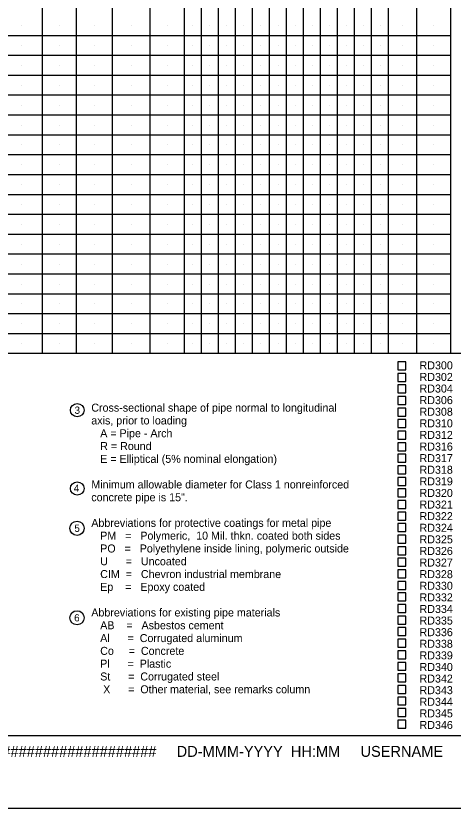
# Model space of a CAD drawing. Extents: x -1700 to 0, y 0 to 1100.
# Drawn here: x -1388 to -1087, y 0 to 545 of the extents above; entities that cross this region are included whole.
import ezdxf

# ---------------------------------------------------------------- set-up
doc = ezdxf.new("R2010")
doc.units = 0
for name, color, linetype in [('#plot_border', 7, 'Continuous'), ('#plot_shape', 7, 'Continuous'), ('P_ODOT_PLAN_Border', 7, 'Continuous'), ('P_ODOT_PLAN_General', 7, 'Continuous'), ('P_RDWY_PLAN_NotesTx', 7, 'Continuous')]:
    doc.layers.add(name, color=color, linetype=linetype)

msp = doc.modelspace()

# ---------------------------------------------------------------- linework, layer by layer
at = {"layer": '#plot_shape'}
msp.add_lwpolyline([(-1700, 0), (0, 0), (0, 1100), (-1700, 1100)], close=True, dxfattribs=at)
at = {"layer": 'P_ODOT_PLAN_Border'}
msp.add_lwpolyline([(-1625, 50), (-25, 50), (-25, 1050), (-1625, 1050)], close=True, dxfattribs=at)
at = {"layer": 'P_ODOT_PLAN_General'}
for p, q in [((-1271.83, 312.45), (-1271.83, 1050)), ((-1088.42, 312.45), (-1088.42, 1050)), ((-1260.12, 312.45), (-1260.12, 1034.39)), ((-1248.42, 312.45), (-1248.42, 1034.39)), ((-1236.71, 312.45), (-1236.71, 1034.39)), ((-1225, 312.45), (-1225, 1034.39)), ((-1213.3, 312.45), (-1213.3, 1034.39)), ((-1201.59, 312.45), (-1201.59, 1034.39)), ((-1189.88, 312.45), (-1189.88, 1034.39)), ((-1178.17, 312.45), (-1178.17, 1034.39)), ((-1166.47, 312.45), (-1166.47, 1034.39)), ((-1154.76, 312.45), (-1154.76, 1034.39)), ((-1143.05, 312.45), (-1143.05, 1034.39)), ((-1131.35, 312.45), (-1131.35, 1034.39)), ((-1111.83, 312.45), (-1111.83, 1034.39)), ((-1369.39, 312.45), (-1369.39, 1014.88)), ((-1345.98, 312.45), (-1345.98, 1014.88)), ((-1295.47, 312.45), (-1295.47, 952.44)), ((-1321.23, 312.45), (-1321.23, 913.42)), ((-1384.03, 537.81), (-1384.03, 537.81)), ((-1357.68, 537.81), (-1357.68, 537.81)), ((-1333.61, 537.81), (-1333.61, 537.81)), ((-1308.35, 537.81), (-1308.35, 537.81)), ((-1283.65, 537.81), (-1283.65, 537.81)), ((-1265.98, 537.81), (-1265.98, 537.81)), ((-1254.27, 537.81), (-1254.27, 537.81)), ((-1242.56, 537.81), (-1242.56, 537.81)), ((-1230.86, 537.81), (-1230.86, 537.81)), ((-1219.15, 537.81), (-1219.15, 537.81)), ((-1207.44, 537.81), (-1207.44, 537.81)), ((-1195.73, 537.81), (-1195.73, 537.81)), ((-1184.03, 537.81), (-1184.03, 537.81)), ((-1172.32, 537.81), (-1172.32, 537.81)), ((-1160.61, 537.81), (-1160.61, 537.81)), ((-1148.91, 537.81), (-1148.91, 537.81)), ((-1137.2, 537.81), (-1137.2, 537.81)), ((-1121.59, 537.81), (-1121.59, 537.81)), ((-1100.13, 537.81), (-1100.13, 537.81)), ((-1088.42, 530.98), (-1398.66, 530.98)), ((-1384.03, 524.15), (-1384.03, 524.15)), ((-1357.68, 524.15), (-1357.68, 524.15)), ((-1333.61, 524.15), (-1333.61, 524.15)), ((-1308.35, 524.15), (-1308.35, 524.15)), ((-1283.65, 524.15), (-1283.65, 524.15)), ((-1265.98, 524.15), (-1265.98, 524.15)), ((-1254.27, 524.15), (-1254.27, 524.15)), ((-1242.56, 524.15), (-1242.56, 524.15)), ((-1230.86, 524.15), (-1230.86, 524.15)), ((-1219.15, 524.15), (-1219.15, 524.15)), ((-1207.44, 524.15), (-1207.44, 524.15)), ((-1195.73, 524.15), (-1195.73, 524.15)), ((-1184.03, 524.15), (-1184.03, 524.15)), ((-1172.32, 524.15), (-1172.32, 524.15)), ((-1160.61, 524.15), (-1160.61, 524.15)), ((-1148.91, 524.15), (-1148.91, 524.15)), ((-1137.2, 524.15), (-1137.2, 524.15)), ((-1121.59, 524.15), (-1121.59, 524.15)), ((-1100.13, 524.15), (-1100.13, 524.15)), ((-1088.42, 517.32), (-1398.66, 517.32)), ((-1384.03, 510.49), (-1384.03, 510.49)), ((-1357.68, 510.49), (-1357.68, 510.49)), ((-1333.61, 510.49), (-1333.61, 510.49)), ((-1308.35, 510.49), (-1308.35, 510.49)), ((-1283.65, 510.49), (-1283.65, 510.49)), ((-1265.98, 510.49), (-1265.98, 510.49)), ((-1254.27, 510.49), (-1254.27, 510.49)), ((-1242.56, 510.49), (-1242.56, 510.49)), ((-1230.86, 510.49), (-1230.86, 510.49)), ((-1219.15, 510.49), (-1219.15, 510.49)), ((-1207.44, 510.49), (-1207.44, 510.49)), ((-1195.73, 510.49), (-1195.73, 510.49)), ((-1184.03, 510.49), (-1184.03, 510.49)), ((-1172.32, 510.49), (-1172.32, 510.49)), ((-1160.61, 510.49), (-1160.61, 510.49)), ((-1148.91, 510.49), (-1148.91, 510.49)), ((-1137.2, 510.49), (-1137.2, 510.49)), ((-1121.59, 510.49), (-1121.59, 510.49)), ((-1100.13, 510.49), (-1100.13, 510.49)), ((-1088.42, 503.66), (-1398.66, 503.66)), ((-1384.03, 496.83), (-1384.03, 496.83)), ((-1357.68, 496.83), (-1357.68, 496.83)), ((-1333.61, 496.83), (-1333.61, 496.83)), ((-1308.35, 496.83), (-1308.35, 496.83)), ((-1283.65, 496.83), (-1283.65, 496.83)), ((-1265.98, 496.83), (-1265.98, 496.83)), ((-1254.27, 496.83), (-1254.27, 496.83)), ((-1242.56, 496.83), (-1242.56, 496.83)), ((-1230.86, 496.83), (-1230.86, 496.83)), ((-1219.15, 496.83), (-1219.15, 496.83)), ((-1207.44, 496.83), (-1207.44, 496.83)), ((-1195.73, 496.83), (-1195.73, 496.83)), ((-1184.03, 496.83), (-1184.03, 496.83)), ((-1172.32, 496.83), (-1172.32, 496.83)), ((-1160.61, 496.83), (-1160.61, 496.83)), ((-1148.91, 496.83), (-1148.91, 496.83)), ((-1137.2, 496.83), (-1137.2, 496.83)), ((-1121.59, 496.83), (-1121.59, 496.83)), ((-1100.13, 496.83), (-1100.13, 496.83)), ((-1088.42, 490.01), (-1398.66, 490.01)), ((-1384.03, 483.18), (-1384.03, 483.18)), ((-1357.68, 483.18), (-1357.68, 483.18)), ((-1333.61, 483.18), (-1333.61, 483.18)), ((-1308.35, 483.18), (-1308.35, 483.18)), ((-1283.65, 483.18), (-1283.65, 483.18)), ((-1265.98, 483.18), (-1265.98, 483.18)), ((-1254.27, 483.18), (-1254.27, 483.18)), ((-1242.56, 483.18), (-1242.56, 483.18)), ((-1230.86, 483.18), (-1230.86, 483.18)), ((-1219.15, 483.18), (-1219.15, 483.18)), ((-1207.44, 483.18), (-1207.44, 483.18)), ((-1195.73, 483.18), (-1195.73, 483.18)), ((-1184.03, 483.18), (-1184.03, 483.18)), ((-1172.32, 483.18), (-1172.32, 483.18)), ((-1160.61, 483.18), (-1160.61, 483.18)), ((-1148.91, 483.18), (-1148.91, 483.18)), ((-1137.2, 483.18), (-1137.2, 483.18)), ((-1121.59, 483.18), (-1121.59, 483.18)), ((-1100.13, 483.18), (-1100.13, 483.18)), ((-1088.42, 476.35), (-1398.66, 476.35)), ((-1384.03, 469.52), (-1384.03, 469.52)), ((-1357.68, 469.52), (-1357.68, 469.52)), ((-1333.61, 469.52), (-1333.61, 469.52)), ((-1308.35, 469.52), (-1308.35, 469.52)), ((-1283.65, 469.52), (-1283.65, 469.52)), ((-1265.98, 469.52), (-1265.98, 469.52)), ((-1254.27, 469.52), (-1254.27, 469.52)), ((-1242.56, 469.52), (-1242.56, 469.52)), ((-1230.86, 469.52), (-1230.86, 469.52)), ((-1219.15, 469.52), (-1219.15, 469.52)), ((-1207.44, 469.52), (-1207.44, 469.52)), ((-1195.73, 469.52), (-1195.73, 469.52)), ((-1184.03, 469.52), (-1184.03, 469.52)), ((-1172.32, 469.52), (-1172.32, 469.52)), ((-1160.61, 469.52), (-1160.61, 469.52)), ((-1148.91, 469.52), (-1148.91, 469.52)), ((-1137.2, 469.52), (-1137.2, 469.52)), ((-1121.59, 469.52), (-1121.59, 469.52)), ((-1100.13, 469.52), (-1100.13, 469.52)), ((-1088.42, 462.69), (-1398.66, 462.69)), ((-1384.03, 455.86), (-1384.03, 455.86)), ((-1357.68, 455.86), (-1357.68, 455.86)), ((-1333.61, 455.86), (-1333.61, 455.86)), ((-1308.35, 455.86), (-1308.35, 455.86)), ((-1283.65, 455.86), (-1283.65, 455.86)), ((-1265.98, 455.86), (-1265.98, 455.86)), ((-1254.27, 455.86), (-1254.27, 455.86)), ((-1242.56, 455.86), (-1242.56, 455.86)), ((-1230.86, 455.86), (-1230.86, 455.86)), ((-1219.15, 455.86), (-1219.15, 455.86)), ((-1207.44, 455.86), (-1207.44, 455.86)), ((-1195.73, 455.86), (-1195.73, 455.86)), ((-1184.03, 455.86), (-1184.03, 455.86)), ((-1172.32, 455.86), (-1172.32, 455.86)), ((-1160.61, 455.86), (-1160.61, 455.86)), ((-1148.91, 455.86), (-1148.91, 455.86)), ((-1137.2, 455.86), (-1137.2, 455.86)), ((-1121.59, 455.86), (-1121.59, 455.86)), ((-1100.13, 455.86), (-1100.13, 455.86)), ((-1088.42, 449.03), (-1398.66, 449.03)), ((-1384.03, 442.2), (-1384.03, 442.2)), ((-1357.68, 442.2), (-1357.68, 442.2)), ((-1333.61, 442.2), (-1333.61, 442.2)), ((-1308.35, 442.2), (-1308.35, 442.2)), ((-1283.65, 442.2), (-1283.65, 442.2)), ((-1265.98, 442.2), (-1265.98, 442.2)), ((-1254.27, 442.2), (-1254.27, 442.2)), ((-1242.56, 442.2), (-1242.56, 442.2)), ((-1230.86, 442.2), (-1230.86, 442.2)), ((-1219.15, 442.2), (-1219.15, 442.2)), ((-1207.44, 442.2), (-1207.44, 442.2)), ((-1195.73, 442.2), (-1195.73, 442.2)), ((-1184.03, 442.2), (-1184.03, 442.2)), ((-1172.32, 442.2), (-1172.32, 442.2)), ((-1160.61, 442.2), (-1160.61, 442.2)), ((-1148.91, 442.2), (-1148.91, 442.2)), ((-1137.2, 442.2), (-1137.2, 442.2)), ((-1121.59, 442.2), (-1121.59, 442.2)), ((-1100.13, 442.2), (-1100.13, 442.2)), ((-1088.42, 435.37), (-1398.66, 435.37)), ((-1384.03, 428.54), (-1384.03, 428.54)), ((-1357.68, 428.54), (-1357.68, 428.54)), ((-1333.61, 428.54), (-1333.61, 428.54)), ((-1308.35, 428.54), (-1308.35, 428.54)), ((-1283.65, 428.54), (-1283.65, 428.54)), ((-1265.98, 428.54), (-1265.98, 428.54)), ((-1254.27, 428.54), (-1254.27, 428.54)), ((-1242.56, 428.54), (-1242.56, 428.54)), ((-1230.86, 428.54), (-1230.86, 428.54)), ((-1219.15, 428.54), (-1219.15, 428.54)), ((-1207.44, 428.54), (-1207.44, 428.54)), ((-1195.73, 428.54), (-1195.73, 428.54)), ((-1184.03, 428.54), (-1184.03, 428.54)), ((-1172.32, 428.54), (-1172.32, 428.54)), ((-1160.61, 428.54), (-1160.61, 428.54)), ((-1148.91, 428.54), (-1148.91, 428.54)), ((-1137.2, 428.54), (-1137.2, 428.54)), ((-1121.59, 428.54), (-1121.59, 428.54)), ((-1100.13, 428.54), (-1100.13, 428.54)), ((-1088.42, 421.71), (-1398.66, 421.71)), ((-1384.03, 414.88), (-1384.03, 414.88)), ((-1357.68, 414.88), (-1357.68, 414.88)), ((-1333.61, 414.88), (-1333.61, 414.88)), ((-1308.35, 414.88), (-1308.35, 414.88)), ((-1283.65, 414.88), (-1283.65, 414.88)), ((-1265.98, 414.88), (-1265.98, 414.88)), ((-1254.27, 414.88), (-1254.27, 414.88)), ((-1242.56, 414.88), (-1242.56, 414.88)), ((-1230.86, 414.88), (-1230.86, 414.88)), ((-1219.15, 414.88), (-1219.15, 414.88)), ((-1207.44, 414.88), (-1207.44, 414.88)), ((-1195.73, 414.88), (-1195.73, 414.88)), ((-1184.03, 414.88), (-1184.03, 414.88)), ((-1172.32, 414.88), (-1172.32, 414.88)), ((-1160.61, 414.88), (-1160.61, 414.88)), ((-1148.91, 414.88), (-1148.91, 414.88)), ((-1137.2, 414.88), (-1137.2, 414.88)), ((-1121.59, 414.88), (-1121.59, 414.88)), ((-1100.13, 414.88), (-1100.13, 414.88)), ((-1088.42, 408.06), (-1398.66, 408.06)), ((-1384.03, 401.23), (-1384.03, 401.23)), ((-1357.68, 401.23), (-1357.68, 401.23)), ((-1333.61, 401.23), (-1333.61, 401.23)), ((-1308.35, 401.23), (-1308.35, 401.23)), ((-1283.65, 401.23), (-1283.65, 401.23)), ((-1265.98, 401.23), (-1265.98, 401.23)), ((-1254.27, 401.23), (-1254.27, 401.23)), ((-1242.56, 401.23), (-1242.56, 401.23)), ((-1230.86, 401.23), (-1230.86, 401.23)), ((-1219.15, 401.23), (-1219.15, 401.23)), ((-1207.44, 401.23), (-1207.44, 401.23)), ((-1195.73, 401.23), (-1195.73, 401.23)), ((-1184.03, 401.23), (-1184.03, 401.23)), ((-1172.32, 401.23), (-1172.32, 401.23)), ((-1160.61, 401.23), (-1160.61, 401.23)), ((-1148.91, 401.23), (-1148.91, 401.23)), ((-1137.2, 401.23), (-1137.2, 401.23)), ((-1121.59, 401.23), (-1121.59, 401.23)), ((-1100.13, 401.23), (-1100.13, 401.23)), ((-1088.42, 394.4), (-1398.66, 394.4)), ((-1384.03, 387.57), (-1384.03, 387.57)), ((-1357.68, 387.57), (-1357.68, 387.57)), ((-1333.61, 387.57), (-1333.61, 387.57)), ((-1308.35, 387.57), (-1308.35, 387.57)), ((-1283.65, 387.57), (-1283.65, 387.57)), ((-1265.98, 387.57), (-1265.98, 387.57)), ((-1254.27, 387.57), (-1254.27, 387.57)), ((-1242.56, 387.57), (-1242.56, 387.57)), ((-1230.86, 387.57), (-1230.86, 387.57)), ((-1219.15, 387.57), (-1219.15, 387.57)), ((-1207.44, 387.57), (-1207.44, 387.57)), ((-1195.73, 387.57), (-1195.73, 387.57)), ((-1184.03, 387.57), (-1184.03, 387.57)), ((-1172.32, 387.57), (-1172.32, 387.57)), ((-1160.61, 387.57), (-1160.61, 387.57)), ((-1148.91, 387.57), (-1148.91, 387.57)), ((-1137.2, 387.57), (-1137.2, 387.57)), ((-1121.59, 387.57), (-1121.59, 387.57)), ((-1100.13, 387.57), (-1100.13, 387.57)), ((-1088.42, 380.74), (-1398.66, 380.74)), ((-1384.03, 373.91), (-1384.03, 373.91)), ((-1357.68, 373.91), (-1357.68, 373.91)), ((-1333.61, 373.91), (-1333.61, 373.91)), ((-1308.35, 373.91), (-1308.35, 373.91)), ((-1283.65, 373.91), (-1283.65, 373.91)), ((-1265.98, 373.91), (-1265.98, 373.91)), ((-1254.27, 373.91), (-1254.27, 373.91)), ((-1242.56, 373.91), (-1242.56, 373.91)), ((-1230.86, 373.91), (-1230.86, 373.91)), ((-1219.15, 373.91), (-1219.15, 373.91)), ((-1207.44, 373.91), (-1207.44, 373.91)), ((-1195.73, 373.91), (-1195.73, 373.91)), ((-1184.03, 373.91), (-1184.03, 373.91)), ((-1172.32, 373.91), (-1172.32, 373.91)), ((-1160.61, 373.91), (-1160.61, 373.91)), ((-1148.91, 373.91), (-1148.91, 373.91)), ((-1137.2, 373.91), (-1137.2, 373.91)), ((-1121.59, 373.91), (-1121.59, 373.91)), ((-1100.13, 373.91), (-1100.13, 373.91)), ((-1088.42, 367.08), (-1398.66, 367.08)), ((-1384.03, 360.25), (-1384.03, 360.25)), ((-1357.68, 360.25), (-1357.68, 360.25)), ((-1333.61, 360.25), (-1333.61, 360.25)), ((-1308.35, 360.25), (-1308.35, 360.25)), ((-1283.65, 360.25), (-1283.65, 360.25)), ((-1265.98, 360.25), (-1265.98, 360.25)), ((-1254.27, 360.25), (-1254.27, 360.25)), ((-1242.56, 360.25), (-1242.56, 360.25)), ((-1230.86, 360.25), (-1230.86, 360.25)), ((-1219.15, 360.25), (-1219.15, 360.25)), ((-1207.44, 360.25), (-1207.44, 360.25)), ((-1195.73, 360.25), (-1195.73, 360.25)), ((-1184.03, 360.25), (-1184.03, 360.25)), ((-1172.32, 360.25), (-1172.32, 360.25)), ((-1160.61, 360.25), (-1160.61, 360.25)), ((-1148.91, 360.25), (-1148.91, 360.25)), ((-1137.2, 360.25), (-1137.2, 360.25)), ((-1121.59, 360.25), (-1121.59, 360.25)), ((-1100.13, 360.25), (-1100.13, 360.25)), ((-1088.42, 353.42), (-1398.66, 353.42)), ((-1384.03, 346.59), (-1384.03, 346.59)), ((-1357.68, 346.59), (-1357.68, 346.59)), ((-1333.61, 346.59), (-1333.61, 346.59)), ((-1308.35, 346.59), (-1308.35, 346.59)), ((-1283.65, 346.59), (-1283.65, 346.59)), ((-1265.98, 346.59), (-1265.98, 346.59)), ((-1254.27, 346.59), (-1254.27, 346.59)), ((-1242.56, 346.59), (-1242.56, 346.59)), ((-1230.86, 346.59), (-1230.86, 346.59)), ((-1219.15, 346.59), (-1219.15, 346.59)), ((-1207.44, 346.59), (-1207.44, 346.59)), ((-1195.73, 346.59), (-1195.73, 346.59)), ((-1184.03, 346.59), (-1184.03, 346.59)), ((-1172.32, 346.59), (-1172.32, 346.59)), ((-1160.61, 346.59), (-1160.61, 346.59)), ((-1148.91, 346.59), (-1148.91, 346.59)), ((-1137.2, 346.59), (-1137.2, 346.59)), ((-1121.59, 346.59), (-1121.59, 346.59)), ((-1100.13, 346.59), (-1100.13, 346.59)), ((-1088.42, 339.76), (-1398.66, 339.76)), ((-1384.03, 332.93), (-1384.03, 332.93)), ((-1357.68, 332.93), (-1357.68, 332.93)), ((-1333.61, 332.93), (-1333.61, 332.93)), ((-1308.35, 332.93), (-1308.35, 332.93)), ((-1283.65, 332.93), (-1283.65, 332.93)), ((-1265.98, 332.93), (-1265.98, 332.93)), ((-1254.27, 332.93), (-1254.27, 332.93)), ((-1242.56, 332.93), (-1242.56, 332.93)), ((-1230.86, 332.93), (-1230.86, 332.93)), ((-1219.15, 332.93), (-1219.15, 332.93)), ((-1207.44, 332.93), (-1207.44, 332.93)), ((-1195.73, 332.93), (-1195.73, 332.93)), ((-1184.03, 332.93), (-1184.03, 332.93)), ((-1172.32, 332.93), (-1172.32, 332.93)), ((-1160.61, 332.93), (-1160.61, 332.93)), ((-1148.91, 332.93), (-1148.91, 332.93)), ((-1137.2, 332.93), (-1137.2, 332.93)), ((-1121.59, 332.93), (-1121.59, 332.93)), ((-1100.13, 332.93), (-1100.13, 332.93)), ((-1088.42, 326.1), (-1398.66, 326.1)), ((-1384.03, 319.28), (-1384.03, 319.28)), ((-1357.68, 319.28), (-1357.68, 319.28)), ((-1333.61, 319.28), (-1333.61, 319.28)), ((-1308.35, 319.28), (-1308.35, 319.28)), ((-1283.65, 319.28), (-1283.65, 319.28)), ((-1265.98, 319.28), (-1265.98, 319.28)), ((-1254.27, 319.28), (-1254.27, 319.28)), ((-1242.56, 319.28), (-1242.56, 319.28)), ((-1230.86, 319.28), (-1230.86, 319.28)), ((-1219.15, 319.28), (-1219.15, 319.28)), ((-1207.44, 319.28), (-1207.44, 319.28)), ((-1195.73, 319.28), (-1195.73, 319.28)), ((-1184.03, 319.28), (-1184.03, 319.28)), ((-1172.32, 319.28), (-1172.32, 319.28)), ((-1160.61, 319.28), (-1160.61, 319.28)), ((-1148.91, 319.28), (-1148.91, 319.28)), ((-1137.2, 319.28), (-1137.2, 319.28)), ((-1121.59, 319.28), (-1121.59, 319.28)), ((-1100.13, 319.28), (-1100.13, 319.28)), ((-25.02, 312.45), (-1625, 312.45))]:
    msp.add_line(p, q, dxfattribs=at)
at = {"layer": 'P_RDWY_PLAN_NotesTx'}
for points in [[(-1119.52, 306.81), (-1124.99, 306.81), (-1124.99, 301.34), (-1119.52, 301.34)], [(-1119.52, 298.86), (-1124.99, 298.86), (-1124.99, 293.39), (-1119.52, 293.39)], [(-1119.52, 290.92), (-1124.99, 290.92), (-1124.99, 285.45), (-1119.52, 285.45)], [(-1119.52, 282.97), (-1124.99, 282.97), (-1124.99, 277.5), (-1119.52, 277.5)], [(-1119.52, 275.03), (-1124.99, 275.03), (-1124.99, 269.56), (-1119.52, 269.56)], [(-1119.52, 267.08), (-1124.99, 267.08), (-1124.99, 261.61), (-1119.52, 261.61)], [(-1119.52, 259.14), (-1124.99, 259.14), (-1124.99, 253.67), (-1119.52, 253.67)], [(-1119.52, 251.19), (-1124.99, 251.19), (-1124.99, 245.72), (-1119.52, 245.72)], [(-1119.52, 243.25), (-1124.99, 243.25), (-1124.99, 237.78), (-1119.52, 237.78)], [(-1119.52, 235.3), (-1124.99, 235.3), (-1124.99, 229.83), (-1119.52, 229.83)], [(-1119.52, 227.35), (-1124.99, 227.35), (-1124.99, 221.88), (-1119.52, 221.88)], [(-1119.52, 219.41), (-1124.99, 219.41), (-1124.99, 213.94), (-1119.52, 213.94)], [(-1119.52, 211.46), (-1124.99, 211.46), (-1124.99, 205.99), (-1119.52, 205.99)], [(-1119.52, 203.52), (-1124.99, 203.52), (-1124.99, 198.05), (-1119.52, 198.05)], [(-1119.52, 195.57), (-1124.99, 195.57), (-1124.99, 190.1), (-1119.52, 190.1)], [(-1119.52, 187.63), (-1124.99, 187.63), (-1124.99, 182.16), (-1119.52, 182.16)], [(-1119.52, 179.68), (-1124.99, 179.68), (-1124.99, 174.21), (-1119.52, 174.21)], [(-1119.52, 171.74), (-1124.99, 171.74), (-1124.99, 166.27), (-1119.52, 166.27)], [(-1119.52, 163.79), (-1124.99, 163.79), (-1124.99, 158.32), (-1119.52, 158.32)], [(-1119.52, 155.85), (-1124.99, 155.85), (-1124.99, 150.38), (-1119.52, 150.38)], [(-1119.52, 147.9), (-1124.99, 147.9), (-1124.99, 142.43), (-1119.52, 142.43)], [(-1119.52, 139.96), (-1124.99, 139.96), (-1124.99, 134.49), (-1119.52, 134.49)], [(-1119.52, 132.01), (-1124.99, 132.01), (-1124.99, 126.54), (-1119.52, 126.54)], [(-1119.52, 124.07), (-1124.99, 124.07), (-1124.99, 118.6), (-1119.52, 118.6)], [(-1119.52, 116.12), (-1124.99, 116.12), (-1124.99, 110.65), (-1119.52, 110.65)], [(-1119.52, 108.18), (-1124.99, 108.18), (-1124.99, 102.71), (-1119.52, 102.71)], [(-1119.52, 100.23), (-1124.99, 100.23), (-1124.99, 94.76), (-1119.52, 94.76)], [(-1119.52, 92.29), (-1124.99, 92.29), (-1124.99, 86.82), (-1119.52, 86.82)], [(-1119.52, 84.34), (-1124.99, 84.34), (-1124.99, 78.87), (-1119.52, 78.87)], [(-1119.52, 76.39), (-1124.99, 76.39), (-1124.99, 70.92), (-1119.52, 70.92)], [(-1119.52, 68.45), (-1124.99, 68.45), (-1124.99, 62.98), (-1119.52, 62.98)], [(-1119.52, 60.5), (-1124.99, 60.5), (-1124.99, 55.03), (-1119.52, 55.03)]]:
    msp.add_lwpolyline(points, close=True, dxfattribs=at)
for centre in [(-1345.73, 192.4), (-1345.73, 130.86)]:
    msp.add_circle(centre, 4.88, dxfattribs=at)
for centre in [(-1345.58, 273.57), (-1345.58, 219.71)]:
    msp.add_ellipse(centre, major_axis=(4.68, 0), ratio=0.960077, dxfattribs=at)

# ---------------------------------------------------------------- texts
at = {"layer": '#plot_border'}
msp.add_text('THIS IS THE FILENAME LOCATION ##############################     DD-MMM-YYYY  HH:MM     USERNAME', height=7.5, dxfattribs=at).set_placement((-1626.17, 35.27))
at = {"layer": 'P_RDWY_PLAN_NotesTx'}
for s, height, p in [('RD300', 5.5, (-1110.06, 301.65)), ('RD302', 5.5, (-1110.06, 293.67)), ('RD304', 5.5, (-1110.06, 285.7)), ('RD306', 5.5, (-1110.06, 277.72)), ('Cross-sectional shape of pipe normal to longitudinal', 5.5, (-1335.89, 272.56)), ('3', 5, (-1347.39, 271.07)), ('RD308', 5.5, (-1110.06, 269.75)), ('axis, prior to loading', 5.5, (-1335.89, 263.76)), ('RD310', 5.5, (-1110.06, 261.77)), ('   A = Pipe - Arch', 5.5, (-1335.89, 254.96)), ('RD312', 5.5, (-1110.06, 253.8)), ('   R = Round', 5.5, (-1335.89, 246.16)), ('RD316', 5.5, (-1110.06, 245.82)), ('   E = Elliptical (5% nominal elongation)', 5.5, (-1335.89, 237.36)), ('RD317', 5.5, (-1110.06, 237.85)), ('RD318', 5.5, (-1110.06, 229.87)), ('Minimum allowable diameter for Class 1 nonreinforced', 5.5, (-1335.89, 219.76)), ('RD319', 5.5, (-1110.06, 221.9)), ('4', 5, (-1347.93, 217.45)), ('RD320', 5.5, (-1110.06, 213.92)), ('concrete pipe is 15".', 5.5, (-1335.89, 210.96)), ('RD321', 5.5, (-1110.06, 205.95)), ('RD322', 5.5, (-1110.06, 197.97)), ('Abbreviations for protective coatings for metal pipe', 5.5, (-1335.89, 193.36)), ('5', 5, (-1347.51, 189.9)), ('RD324', 5.5, (-1110.06, 190)), ('   PM   =   Polymeric,  10 Mil. thkn. coated both sides', 5.5, (-1335.89, 184.56)), ('RD325', 5.5, (-1110.06, 182.02)), ('   PO   =   Polyethylene inside lining, polymeric outside', 5.5, (-1335.89, 175.76)), ('RD326', 5.5, (-1110.06, 174.05)), ('   U      =   Uncoated', 5.5, (-1335.89, 166.96)), ('RD327', 5.5, (-1110.06, 166.07)), ('   CIM  =   Chevron industrial membrane', 5.5, (-1335.89, 158.16)), ('RD328', 5.5, (-1110.06, 158.1)), ('   Ep    =   Epoxy coated', 5.5, (-1335.89, 149.36)), ('RD330', 5.5, (-1110.06, 150.12)), ('RD332', 5.5, (-1110.06, 142.15)), ('Abbreviations for existing pipe materials', 5.5, (-1335.89, 131.76)), ('RD334', 5.5, (-1110.06, 134.17)), ('6', 5, (-1347.67, 128.36)), ('RD335', 5.5, (-1110.06, 126.2)), ('   AB    =   Asbestos cement', 5.5, (-1335.89, 122.96)), ('   Al      =  Corrugated aluminum', 5.5, (-1335.89, 114.16)), ('RD336', 5.5, (-1110.06, 118.22)), ('RD338', 5.5, (-1110.06, 110.25)), ('   Co     =  Concrete', 5.5, (-1335.89, 105.36)), ('RD339', 5.5, (-1110.06, 102.27)), ('   Pl      =  Plastic', 5.5, (-1335.89, 96.56)), ('RD340', 5.5, (-1110.06, 94.3)), ('   St      =  Corrugated steel', 5.5, (-1335.89, 87.76)), ('RD342', 5.5, (-1110.06, 86.32)), ('    X      =  Other material, see remarks column', 5.5, (-1335.89, 78.96)), ('RD343', 5.5, (-1110.06, 78.35)), ('RD344', 5.5, (-1110.06, 70.37)), ('RD345', 5.5, (-1110.06, 62.4)), ('RD346', 5.5, (-1110.06, 54.42))]:
    msp.add_text(s, height=height, dxfattribs=at).set_placement(p)

doc.saveas('drawing.dxf')
